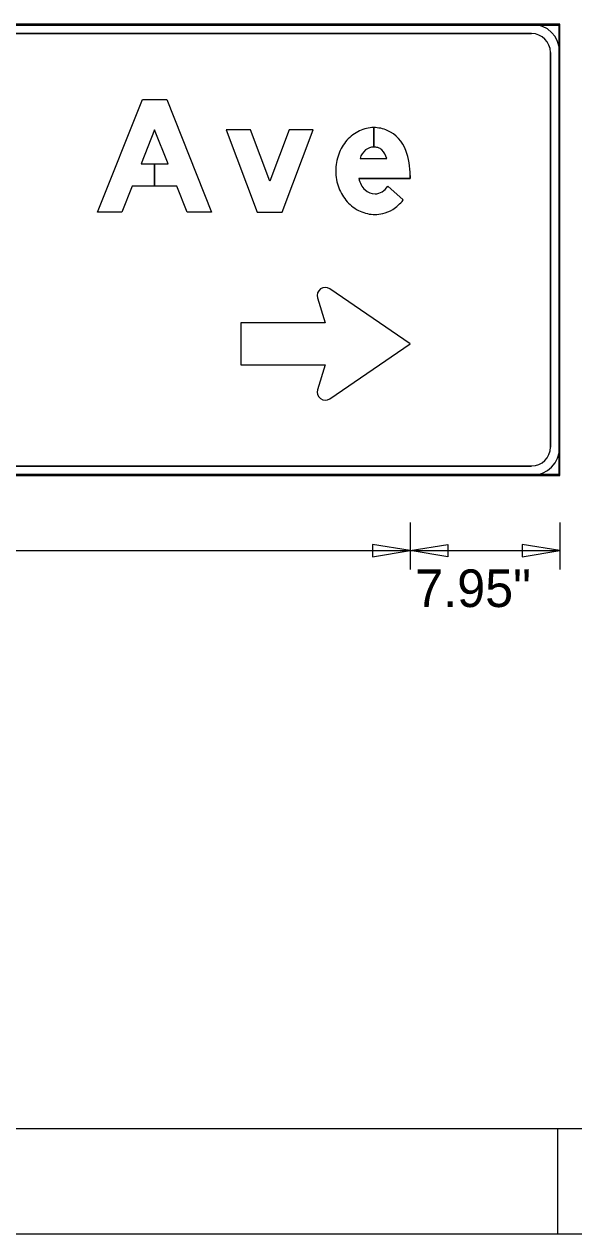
# Model space of a CAD drawing. Extents: x 1374 to 1480, y 568 to 638.
# Drawn here: x 1421.49 to 1423.92, y 595.39 to 600.75 of the extents above; entities that cross this region are included whole.
import ezdxf

# ---------------------------------------------------------------- set-up
doc = ezdxf.new("R2010")
doc.units = 0
for name, color, linetype in [('GSBWFill', 7, 'Continuous'), ('GSColorFill', 7, 'Continuous'), ('GSDims', 7, 'Continuous'), ('GSOutline', 7, 'Continuous'), ('SheetLinesMisc2_dp', 7, 'Continuous')]:
    doc.layers.add(name, color=color, linetype=linetype)

msp = doc.modelspace()

# ---------------------------------------------------------------- linework, layer by layer
at = {"layer": 'GSBWFill'}
for p, q in [((1423.8581, 600.7496), (1414.8581, 600.7496)), ((1423.7331, 600.7496), (1414.9831, 600.7496)), ((1414.9831, 600.7079), (1423.7331, 600.7079)), ((1423.8581, 598.7496), (1423.8581, 600.7496)), ((1423.8165, 600.6246), (1423.8165, 598.8746)), ((1423.8581, 598.8746), (1423.8581, 600.6246)), ((1423.0341, 600.2912), (1423.0341, 600.205)), ((1423.0342, 600.205), (1423.0342, 600.2912)), ((1422.9731, 600.1549), (1423.0916, 600.1549)), ((1423.0956, 600.031), (1423.164, 599.9704)), ((1423.7331, 598.7912), (1414.9835, 598.7912)), ((1414.8581, 598.7496), (1423.8581, 598.7496)), ((1414.9835, 598.7496), (1423.7331, 598.7496))]:
    msp.add_line(p, q, dxfattribs=at)
for points in [[(1422.0631, 600.1312), (1422.0631, 600.0312), (1421.9639, 600.0312), (1421.9182, 599.9162), (1421.8106, 599.9162), (1422.0093, 600.4162), (1422.1169, 600.4162), (1422.3156, 599.9162), (1422.208, 599.9162), (1422.1623, 600.0312), (1422.0632, 600.0312), (1422.0632, 600.1312), (1422.1226, 600.1312), (1422.0631, 600.2808), (1422.0037, 600.1312)], [(1422.4875, 600.2812), (1422.3806, 600.2812), (1422.5181, 599.9162), (1422.6281, 599.9162), (1422.7656, 600.2812), (1422.6588, 600.2812), (1422.5731, 600.0539)]]:
    msp.add_lwpolyline(points, close=True, dxfattribs=at)
for points in [[(1423.1956, 600.0791), (1423.1956, 600.0649), (1422.9674, 600.0649)], [(1422.8397, 599.0892), (1423.1956, 599.3329), (1422.8397, 599.5766)], [(1422.7848, 599.5362), (1422.8188, 599.4257), (1422.4456, 599.4257)], [(1422.4456, 599.4257), (1422.4456, 599.2401), (1422.8188, 599.2401), (1422.7848, 599.1296)]]:
    msp.add_lwpolyline(points, dxfattribs=at)
for centre, radius, start, end in [((1423.7331, 600.6246), 0.125, 0, 90), ((1423.7331, 600.6246), 0.0833, 0, 90), ((1423.0443, 600.1216), 0.1719, 115.3224, 138.8015), ((1423.0341, 600.1431), 0.1481, 90, 115.3224), ((1423.0341, 600.1431), 0.1481, 66.2413, 89.9903), ((1423.0304, 600.1372), 0.155, 19.9901, 65.8469), ((1423.0602, 600.1077), 0.193, 138.8015, 160.0695), ((1423.085, 600.0987), 0.2194, 160.0695, 180), ((1423.0483, 600.132), 0.0786, 130.2868, 163.0777), ((1423.0341, 600.147), 0.058, 90, 129.2086), ((1423.0341, 600.1378), 0.0672, 74.2341, 89.9787), ((1423.0422, 600.1664), 0.0375, 43.3306, 74.2341), ((1422.9975, 600.1242), 0.099, 18.0656, 43.3306), ((1422.8706, 600.0791), 0.325, 0, 19.9901), ((1423.0785, 600.0987), 0.2129, 180, 200.5021), ((1423.0635, 600.0861), 0.0984, 192.4467, 226.2893), ((1423.0594, 600.0916), 0.1925, 200.5021, 222.0738), ((1423.0403, 600.0622), 0.0651, 226.5476, 269.2365), ((1423.0345, 600.0687), 0.0718, 273.8929, 328.2838), ((1423.0472, 600.0806), 0.1761, 222.0738, 245.3524), ((1423.0174, 600.0852), 0.1862, 302.591, 321.9228), ((1423.0394, 600.0635), 0.1573, 245.3524, 270), ((1423.0394, 600.0635), 0.1573, 270, 282.4743), ((1423.0437, 600.0442), 0.1375, 282.4743, 302.591), ((1422.8193, 599.5468), 0.0361, 55.6003, 197.0573), ((1422.8193, 599.119), 0.0361, 162.9427, 304.3997), ((1423.7331, 598.8746), 0.125, 270, 0), ((1423.7331, 598.8746), 0.0833, 270, 0)]:
    msp.add_arc(centre, radius, start, end, dxfattribs=at)
at = {"layer": 'GSColorFill'}
for p, q in [((1423.8581, 600.7496), (1414.8581, 600.7496)), ((1423.8581, 600.7496), (1414.8581, 600.7496)), ((1414.8623, 600.7454), (1423.854, 600.7454)), ((1423.7331, 600.7496), (1414.9831, 600.7496)), ((1414.9831, 600.7079), (1423.7331, 600.7079)), ((1423.854, 600.7454), (1423.854, 598.7537)), ((1423.8581, 598.7496), (1423.8581, 600.7496)), ((1423.8581, 598.7496), (1423.8581, 600.7496)), ((1423.8165, 600.6246), (1423.8165, 598.8746)), ((1423.8581, 598.8746), (1423.8581, 600.6246)), ((1423.0341, 600.2912), (1423.0341, 600.205)), ((1423.0342, 600.205), (1423.0342, 600.2912)), ((1422.9731, 600.1549), (1423.0916, 600.1549)), ((1423.0956, 600.031), (1423.164, 599.9704)), ((1423.7331, 598.7912), (1414.9835, 598.7912)), ((1423.854, 598.7537), (1414.8581, 598.7537)), ((1414.8581, 598.7496), (1423.8581, 598.7496)), ((1414.8581, 598.7496), (1423.8581, 598.7496)), ((1414.9835, 598.7496), (1423.7331, 598.7496))]:
    msp.add_line(p, q, dxfattribs=at)
for points in [[(1422.0631, 600.1312), (1422.0631, 600.0312), (1421.9639, 600.0312), (1421.9182, 599.9162), (1421.8106, 599.9162), (1422.0093, 600.4162), (1422.1169, 600.4162), (1422.3156, 599.9162), (1422.208, 599.9162), (1422.1623, 600.0312), (1422.0632, 600.0312), (1422.0632, 600.1312), (1422.1226, 600.1312), (1422.0631, 600.2808), (1422.0037, 600.1312)], [(1422.4875, 600.2812), (1422.3806, 600.2812), (1422.5181, 599.9162), (1422.6281, 599.9162), (1422.7656, 600.2812), (1422.6588, 600.2812), (1422.5731, 600.0539)]]:
    msp.add_lwpolyline(points, close=True, dxfattribs=at)
for points in [[(1423.1956, 600.0791), (1423.1956, 600.0649), (1422.9674, 600.0649)], [(1422.8397, 599.0892), (1423.1956, 599.3329), (1422.8397, 599.5766)], [(1422.7848, 599.5362), (1422.8188, 599.4257), (1422.4456, 599.4257)], [(1422.4456, 599.4257), (1422.4456, 599.2401), (1422.8188, 599.2401), (1422.7848, 599.1296)]]:
    msp.add_lwpolyline(points, dxfattribs=at)
for centre, radius, start, end in [((1423.7331, 600.6246), 0.125, 0, 90), ((1423.7331, 600.6246), 0.0833, 0, 90), ((1423.0443, 600.1216), 0.1719, 115.3224, 138.8015), ((1423.0341, 600.1431), 0.1481, 90, 115.3224), ((1423.0341, 600.1431), 0.1481, 66.2413, 89.9903), ((1423.0304, 600.1372), 0.155, 19.9901, 65.8469), ((1423.0602, 600.1077), 0.193, 138.8015, 160.0695), ((1423.085, 600.0987), 0.2194, 160.0695, 180), ((1423.0483, 600.132), 0.0786, 130.2868, 163.0777), ((1423.0341, 600.147), 0.058, 90, 129.2086), ((1423.0341, 600.1378), 0.0672, 74.2341, 89.9787), ((1423.0422, 600.1664), 0.0375, 43.3306, 74.2341), ((1422.9975, 600.1242), 0.099, 18.0656, 43.3306), ((1422.8706, 600.0791), 0.325, 0, 19.9901), ((1423.0785, 600.0987), 0.2129, 180, 200.5021), ((1423.0635, 600.0861), 0.0984, 192.4467, 226.2893), ((1423.0594, 600.0916), 0.1925, 200.5021, 222.0738), ((1423.0403, 600.0622), 0.0651, 226.5476, 269.2365), ((1423.0345, 600.0687), 0.0718, 273.8929, 328.2838), ((1423.0472, 600.0806), 0.1761, 222.0738, 245.3524), ((1423.0174, 600.0852), 0.1862, 302.591, 321.9228), ((1423.0394, 600.0635), 0.1573, 245.3524, 270), ((1423.0394, 600.0635), 0.1573, 270, 282.4743), ((1423.0437, 600.0442), 0.1375, 282.4743, 302.591), ((1422.8193, 599.5468), 0.0361, 55.6003, 197.0573), ((1422.8193, 599.119), 0.0361, 162.9427, 304.3997), ((1423.7331, 598.8746), 0.125, 270, 0), ((1423.7331, 598.8746), 0.0833, 270, 0)]:
    msp.add_arc(centre, radius, start, end, dxfattribs=at)
at = {"layer": 'GSDims'}
for p, q in [((1423.1956, 598.5412), (1423.1956, 598.3329)), ((1423.1956, 598.5412), (1423.1956, 598.3329)), ((1423.8581, 598.5412), (1423.8581, 598.3329)), ((1423.8581, 598.5412), (1423.8581, 598.3329)), ((1415.5206, 598.4162), (1423.1956, 598.4162)), ((1423.1956, 598.4162), (1423.8581, 598.4162))]:
    msp.add_line(p, q, dxfattribs=at)
for points in [[(1423.1956, 598.4162), (1423.029, 598.444), (1423.029, 598.3884)], [(1423.1956, 598.4162), (1423.3623, 598.444), (1423.3623, 598.3884)], [(1423.8581, 598.4162), (1423.6915, 598.444), (1423.6915, 598.3884)]]:
    msp.add_lwpolyline(points, close=True, dxfattribs=at)
at = {"layer": 'GSOutline'}
for p, q in [((1423.8581, 600.7496), (1414.8581, 600.7496)), ((1423.7331, 600.7496), (1414.9831, 600.7496)), ((1423.7331, 600.7079), (1414.9831, 600.7079)), ((1423.8581, 598.7496), (1423.8581, 600.7496)), ((1423.8165, 598.8746), (1423.8165, 600.6246)), ((1423.8581, 598.8746), (1423.8581, 600.6246)), ((1422.9731, 600.1549), (1423.0916, 600.1549)), ((1423.164, 599.9704), (1423.0956, 600.031)), ((1414.9831, 598.7912), (1423.7331, 598.7912)), ((1414.8581, 598.7496), (1423.8581, 598.7496)), ((1414.9831, 598.7496), (1423.7331, 598.7496))]:
    msp.add_line(p, q, dxfattribs=at)
for points in [[(1422.1623, 600.0312), (1421.9639, 600.0312), (1421.9182, 599.9162), (1421.8106, 599.9162), (1422.0093, 600.4162), (1422.1169, 600.4162), (1422.3156, 599.9162), (1422.208, 599.9162)], [(1422.0037, 600.1312), (1422.1226, 600.1312), (1422.0631, 600.2808)], [(1422.4875, 600.2812), (1422.3806, 600.2812), (1422.5181, 599.9162), (1422.6281, 599.9162), (1422.7656, 600.2812), (1422.6588, 600.2812), (1422.5731, 600.0539)]]:
    msp.add_lwpolyline(points, close=True, dxfattribs=at)
for points in [[(1422.9674, 600.0649), (1423.1956, 600.0649), (1423.1956, 600.0791)], [(1422.8397, 599.0892), (1423.1956, 599.3329), (1422.8397, 599.5766)], [(1422.7848, 599.5362), (1422.8188, 599.4257), (1422.4456, 599.4257)], [(1422.4456, 599.4257), (1422.4456, 599.2401), (1422.8188, 599.2401), (1422.7848, 599.1296)]]:
    msp.add_lwpolyline(points, dxfattribs=at)
for centre, radius, start, end in [((1423.7331, 600.6246), 0.125, 0, 90), ((1423.7331, 600.6246), 0.0833, 0, 90), ((1423.0443, 600.1216), 0.1719, 115.3224, 138.8015), ((1423.0341, 600.1431), 0.1481, 90, 115.3224), ((1423.0341, 600.1431), 0.1481, 66.2413, 90), ((1423.0304, 600.1372), 0.155, 19.9901, 65.8469), ((1423.0602, 600.1077), 0.193, 138.8015, 160.0695), ((1423.085, 600.0987), 0.2194, 160.0695, 180), ((1423.0483, 600.132), 0.0786, 130.2868, 163.0777), ((1423.0341, 600.147), 0.058, 90, 129.2086), ((1423.0341, 600.1378), 0.0672, 74.2341, 90), ((1423.0422, 600.1664), 0.0375, 43.3306, 74.2341), ((1422.9975, 600.1242), 0.099, 18.0656, 43.3306), ((1422.8706, 600.0791), 0.325, 0, 19.9901), ((1423.0785, 600.0987), 0.2129, 180, 200.5021), ((1423.0635, 600.0861), 0.0984, 192.4467, 226.2893), ((1423.0594, 600.0916), 0.1925, 200.5021, 222.0738), ((1423.0403, 600.0622), 0.0651, 226.5476, 269.2365), ((1423.0345, 600.0687), 0.0718, 273.8929, 328.2838), ((1423.0472, 600.0806), 0.1761, 222.0738, 245.3524), ((1423.0174, 600.0852), 0.1862, 302.591, 321.9228), ((1423.0394, 600.0635), 0.1573, 245.3524, 270), ((1423.0394, 600.0635), 0.1573, 270, 282.4743), ((1423.0437, 600.0442), 0.1375, 282.4743, 302.591), ((1422.8193, 599.5468), 0.0361, 55.6003, 197.0573), ((1422.8193, 599.119), 0.0361, 162.9427, 304.3997), ((1423.7331, 598.8746), 0.125, 270, 0), ((1423.7331, 598.8746), 0.0833, 270, 0)]:
    msp.add_arc(centre, radius, start, end, dxfattribs=at)
at = {"layer": 'SheetLinesMisc2_dp'}
for p, q in [((1410.2556, 595.8555), (1428.1633, 595.8555)), ((1423.8473, 595.8555), (1423.8473, 595.3881)), ((1410.2556, 595.3881), (1428.1633, 595.3881))]:
    msp.add_line(p, q, dxfattribs=at)

# ---------------------------------------------------------------- texts
at = {"layer": 'GSDims'}
msp.add_text('7.95"', height=0.16667, dxfattribs=at).set_placement((1423.2174, 598.1662))

doc.saveas('drawing.dxf')
